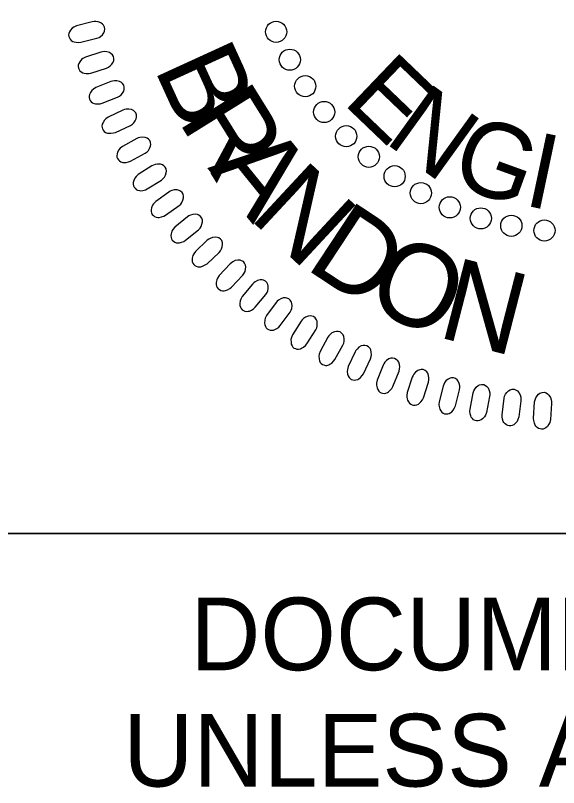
# Model space of a CAD drawing. Extents: x 505602 to 507548, y 483109 to 484209.
# Drawn here: x 507076.9 to 507118, y 484026.9 to 484085.4 of the extents above; entities that cross this region are included whole.
import ezdxf

# ---------------------------------------------------------------- set-up
doc = ezdxf.new("R2010")
doc.units = 0
for name, color, linetype in [('Sheet PE Seal Cell', 7, 'Continuous'), ('Sheet Profile CELL', 7, 'Continuous'), ('Sheet Sticker Exception Certification CELL', 7, 'Continuous')]:
    doc.layers.add(name, color=color, linetype=linetype)

msp = doc.modelspace()

# ---------------------------------------------------------------- linework, layer by layer
at = {"layer": 'Sheet PE Seal Cell'}
for points in [[(507082.689, 484084.884), (507081.501, 484084.579), (507081.298, 484084.488), (507081.175, 484084.403), (507081.039, 484084.252), (507080.957, 484084.131), (507080.907, 484084.002), (507080.895, 484083.891), (507080.903, 484083.777), (507080.95, 484083.674), (507081.009, 484083.566), (507081.093, 484083.479), (507081.216, 484083.403), (507081.308, 484083.364), (507081.469, 484083.336), (507081.658, 484083.323), (507081.818, 484083.341), (507083.037, 484083.645), (507083.196, 484083.709), (507083.32, 484083.788), (507083.452, 484083.914), (507083.56, 484084.057), (507083.613, 484084.171), (507083.632, 484084.339), (507083.614, 484084.488), (507083.538, 484084.623), (507083.464, 484084.712), (507083.336, 484084.811), (507083.142, 484084.884), (507082.951, 484084.905), (507082.818, 484084.901)], [(507083.343, 484082.6), (507082.176, 484082.221), (507081.979, 484082.118), (507081.862, 484082.026), (507081.735, 484081.866), (507081.661, 484081.739), (507081.62, 484081.608), (507081.615, 484081.497), (507081.63, 484081.384), (507081.684, 484081.284), (507081.749, 484081.179), (507081.838, 484081.098), (507081.966, 484081.03), (507082.059, 484080.997), (507082.223, 484080.979), (507082.412, 484080.978), (507082.571, 484081.005), (507083.768, 484081.386), (507083.922, 484081.46), (507084.042, 484081.546), (507084.165, 484081.68), (507084.263, 484081.83), (507084.31, 484081.947), (507084.318, 484082.115), (507084.291, 484082.263), (507084.207, 484082.393), (507084.127, 484082.477), (507083.993, 484082.567), (507083.795, 484082.629), (507083.603, 484082.637), (507083.471, 484082.625)], [(507084.102, 484080.363), (507082.961, 484079.912), (507082.77, 484079.796), (507082.659, 484079.696), (507082.543, 484079.529), (507082.477, 484079.398), (507082.444, 484079.265), (507082.446, 484079.153), (507082.468, 484079.041), (507082.528, 484078.945), (507082.6, 484078.844), (507082.693, 484078.769), (507082.825, 484078.709), (507082.921, 484078.682), (507083.086, 484078.675), (507083.274, 484078.685), (507083.431, 484078.723), (507084.602, 484079.178), (507084.752, 484079.261), (507084.865, 484079.355), (507084.98, 484079.496), (507085.069, 484079.652), (507085.108, 484079.772), (507085.105, 484079.94), (507085.069, 484080.087), (507084.977, 484080.21), (507084.892, 484080.29), (507084.753, 484080.371), (507084.551, 484080.419), (507084.359, 484080.416), (507084.228, 484080.396)], [(507085.001, 484078.203), (507083.891, 484077.681), (507083.709, 484077.554), (507083.604, 484077.447), (507083.499, 484077.273), (507083.441, 484077.139), (507083.416, 484077.003), (507083.425, 484076.892), (507083.454, 484076.782), (507083.52, 484076.689), (507083.598, 484076.594), (507083.697, 484076.524), (507083.832, 484076.472), (507083.929, 484076.452), (507084.093, 484076.455), (507084.281, 484076.477), (507084.435, 484076.524), (507085.576, 484077.052), (507085.719, 484077.145), (507085.827, 484077.245), (507085.932, 484077.393), (507086.012, 484077.554), (507086.043, 484077.677), (507086.03, 484077.844), (507085.984, 484077.988), (507085.884, 484078.106), (507085.794, 484078.18), (507085.651, 484078.253), (507085.446, 484078.288), (507085.255, 484078.273), (507085.125, 484078.245)], [(507086.049, 484076.054), (507084.973, 484075.464), (507084.799, 484075.326), (507084.702, 484075.212), (507084.607, 484075.033), (507084.558, 484074.894), (507084.542, 484074.758), (507084.557, 484074.647), (507084.594, 484074.539), (507084.666, 484074.451), (507084.75, 484074.36), (507084.852, 484074.297), (507084.99, 484074.254), (507085.089, 484074.239), (507085.252, 484074.253), (507085.438, 484074.287), (507085.589, 484074.343), (507086.694, 484074.942), (507086.832, 484075.044), (507086.932, 484075.15), (507087.029, 484075.305), (507087.097, 484075.471), (507087.121, 484075.595), (507087.097, 484075.761), (507087.043, 484075.902), (507086.936, 484076.013), (507086.842, 484076.081), (507086.693, 484076.145), (507086.487, 484076.167), (507086.297, 484076.14), (507086.169, 484076.104)], [(507087.205, 484073.98), (507086.169, 484073.322), (507086.003, 484073.174), (507085.914, 484073.055), (507085.83, 484072.869), (507085.79, 484072.729), (507085.783, 484072.591), (507085.805, 484072.481), (507085.848, 484072.376), (507085.926, 484072.292), (507086.015, 484072.207), (507086.121, 484072.151), (507086.261, 484072.116), (507086.36, 484072.108), (507086.523, 484072.131), (507086.707, 484072.177), (507086.853, 484072.243), (507087.919, 484072.91), (507088.05, 484073.019), (507088.144, 484073.133), (507088.23, 484073.294), (507088.288, 484073.463), (507088.304, 484073.588), (507088.27, 484073.753), (507088.207, 484073.89), (507088.093, 484073.994), (507087.995, 484074.056), (507087.842, 484074.11), (507087.635, 484074.12), (507087.447, 484074.081), (507087.322, 484074.036)], [(507088.482, 484072.005), (507087.488, 484071.284), (507087.333, 484071.125), (507087.25, 484071.001), (507087.179, 484070.81), (507087.148, 484070.667), (507087.149, 484070.529), (507087.178, 484070.422), (507087.228, 484070.318), (507087.31, 484070.24), (507087.405, 484070.161), (507087.515, 484070.111), (507087.657, 484070.085), (507087.756, 484070.084), (507087.917, 484070.117), (507088.097, 484070.174), (507088.24, 484070.249), (507089.261, 484070.982), (507089.385, 484071.1), (507089.471, 484071.218), (507089.548, 484071.384), (507089.595, 484071.557), (507089.603, 484071.683), (507089.559, 484071.845), (507089.487, 484071.978), (507089.367, 484072.075), (507089.265, 484072.13), (507089.11, 484072.175), (507088.903, 484072.172), (507088.717, 484072.121), (507088.595, 484072.069)], [(507089.885, 484070.123), (507088.939, 484069.342), (507088.794, 484069.173), (507088.72, 484069.044), (507088.661, 484068.85), (507088.638, 484068.705), (507088.648, 484068.568), (507088.684, 484068.462), (507088.74, 484068.362), (507088.827, 484068.289), (507088.926, 484068.216), (507089.039, 484068.173), (507089.182, 484068.156), (507089.282, 484068.161), (507089.44, 484068.204), (507089.616, 484068.273), (507089.754, 484068.356), (507090.727, 484069.152), (507090.844, 484069.277), (507090.922, 484069.401), (507090.988, 484069.571), (507091.025, 484069.747), (507091.024, 484069.872), (507090.97, 484070.032), (507090.89, 484070.16), (507090.764, 484070.249), (507090.659, 484070.298), (507090.501, 484070.333), (507090.295, 484070.317), (507090.113, 484070.254), (507089.994, 484070.195)], [(507091.395, 484068.353), (507090.5, 484067.513), (507090.366, 484067.337), (507090.3, 484067.203), (507090.253, 484067.005), (507090.24, 484066.859), (507090.258, 484066.722), (507090.301, 484066.618), (507090.363, 484066.523), (507090.454, 484066.455), (507090.558, 484066.388), (507090.673, 484066.353), (507090.818, 484066.345), (507090.916, 484066.356), (507091.072, 484066.409), (507091.244, 484066.489), (507091.375, 484066.581), (507092.296, 484067.436), (507092.405, 484067.568), (507092.476, 484067.697), (507092.531, 484067.871), (507092.556, 484068.048), (507092.548, 484068.173), (507092.484, 484068.33), (507092.396, 484068.452), (507092.265, 484068.534), (507092.157, 484068.576), (507091.997, 484068.6), (507091.792, 484068.571), (507091.614, 484068.497), (507091.5, 484068.43)], [(507093.131, 484066.575), (507092.29, 484065.681), (507092.167, 484065.495), (507092.11, 484065.358), (507092.075, 484065.157), (507092.071, 484065.01), (507092.098, 484064.876), (507092.147, 484064.776), (507092.215, 484064.684), (507092.31, 484064.622), (507092.419, 484064.562), (507092.535, 484064.533), (507092.68, 484064.535), (507092.778, 484064.552), (507092.93, 484064.614), (507093.096, 484064.705), (507093.222, 484064.805), (507094.088, 484065.716), (507094.187, 484065.855), (507094.25, 484065.988), (507094.294, 484066.165), (507094.308, 484066.343), (507094.292, 484066.468), (507094.219, 484066.619), (507094.123, 484066.737), (507093.987, 484066.81), (507093.876, 484066.845), (507093.716, 484066.86), (507093.513, 484066.817), (507093.34, 484066.733), (507093.23, 484066.659)], [(507094.821, 484065.045), (507094.038, 484064.099), (507093.927, 484063.906), (507093.878, 484063.766), (507093.856, 484063.564), (507093.862, 484063.417), (507093.897, 484063.284), (507093.952, 484063.186), (507094.026, 484063.099), (507094.124, 484063.044), (507094.236, 484062.991), (507094.354, 484062.97), (507094.499, 484062.98), (507094.596, 484063.003), (507094.743, 484063.075), (507094.903, 484063.175), (507095.023, 484063.284), (507095.83, 484064.248), (507095.921, 484064.392), (507095.974, 484064.529), (507096.008, 484064.709), (507096.011, 484064.887), (507095.986, 484065.012), (507095.903, 484065.157), (507095.801, 484065.268), (507095.661, 484065.332), (507095.547, 484065.361), (507095.386, 484065.365), (507095.187, 484065.311), (507095.019, 484065.215), (507094.914, 484065.135)], [(507096.601, 484063.644), (507095.88, 484062.651), (507095.781, 484062.452), (507095.741, 484062.308), (507095.732, 484062.105), (507095.747, 484061.959), (507095.79, 484061.829), (507095.851, 484061.735), (507095.93, 484061.653), (507096.033, 484061.603), (507096.148, 484061.557), (507096.267, 484061.544), (507096.41, 484061.563), (507096.506, 484061.592), (507096.648, 484061.674), (507096.802, 484061.784), (507096.914, 484061.9), (507097.659, 484062.912), (507097.74, 484063.062), (507097.786, 484063.202), (507097.808, 484063.383), (507097.8, 484063.562), (507097.767, 484063.683), (507097.676, 484063.825), (507097.566, 484063.929), (507097.422, 484063.984), (507097.308, 484064.005), (507097.147, 484064), (507096.95, 484063.932), (507096.79, 484063.827), (507096.69, 484063.739)], [(507098.503, 484062.231), (507097.846, 484061.195), (507097.759, 484060.99), (507097.728, 484060.844), (507097.732, 484060.64), (507097.756, 484060.496), (507097.808, 484060.369), (507097.874, 484060.278), (507097.959, 484060.202), (507098.063, 484060.159), (507098.181, 484060.119), (507098.301, 484060.114), (507098.443, 484060.142), (507098.536, 484060.178), (507098.673, 484060.267), (507098.82, 484060.387), (507098.924, 484060.51), (507099.604, 484061.567), (507099.676, 484061.722), (507099.713, 484061.864), (507099.723, 484062.046), (507099.703, 484062.224), (507099.663, 484062.344), (507099.564, 484062.479), (507099.448, 484062.575), (507099.3, 484062.622), (507099.185, 484062.636), (507099.025, 484062.62), (507098.833, 484062.541), (507098.679, 484062.425), (507098.585, 484062.332)], [(507100.521, 484061.015), (507099.93, 484059.941), (507099.857, 484059.73), (507099.835, 484059.583), (507099.852, 484059.38), (507099.884, 484059.237), (507099.944, 484059.113), (507100.016, 484059.028), (507100.105, 484058.956), (507100.212, 484058.92), (507100.332, 484058.888), (507100.452, 484058.89), (507100.592, 484058.927), (507100.683, 484058.968), (507100.814, 484059.067), (507100.953, 484059.195), (507101.05, 484059.324), (507101.662, 484060.422), (507101.723, 484060.581), (507101.751, 484060.725), (507101.75, 484060.908), (507101.72, 484061.084), (507101.673, 484061.201), (507101.564, 484061.329), (507101.442, 484061.419), (507101.292, 484061.456), (507101.176, 484061.463), (507101.017, 484061.437), (507100.831, 484061.345), (507100.685, 484061.221), (507100.596, 484061.122)], [(507102.58, 484059.909), (507102.058, 484058.799), (507101.998, 484058.585), (507101.986, 484058.436), (507102.015, 484058.234), (507102.056, 484058.094), (507102.124, 484057.974), (507102.201, 484057.894), (507102.295, 484057.828), (507102.404, 484057.798), (507102.525, 484057.774), (507102.645, 484057.784), (507102.783, 484057.83), (507102.871, 484057.876), (507102.995, 484057.983), (507103.126, 484058.119), (507103.215, 484058.254), (507103.757, 484059.388), (507103.808, 484059.551), (507103.827, 484059.696), (507103.814, 484059.879), (507103.773, 484060.053), (507103.718, 484060.167), (507103.602, 484060.288), (507103.474, 484060.37), (507103.323, 484060.397), (507103.206, 484060.396), (507103.049, 484060.361), (507102.869, 484060.258), (507102.732, 484060.124), (507102.65, 484060.02)], [(507104.708, 484058.901), (507104.256, 484057.76), (507104.21, 484057.542), (507104.207, 484057.393), (507104.249, 484057.194), (507104.298, 484057.056), (507104.374, 484056.941), (507104.456, 484056.865), (507104.553, 484056.805), (507104.664, 484056.783), (507104.787, 484056.767), (507104.906, 484056.783), (507105.04, 484056.838), (507105.125, 484056.89), (507105.243, 484057.004), (507105.364, 484057.149), (507105.444, 484057.289), (507105.914, 484058.455), (507105.956, 484058.62), (507105.965, 484058.766), (507105.941, 484058.948), (507105.888, 484059.119), (507105.827, 484059.229), (507105.703, 484059.343), (507105.571, 484059.416), (507105.418, 484059.434), (507105.302, 484059.426), (507105.147, 484059.381), (507104.974, 484059.267), (507104.845, 484059.124), (507104.77, 484059.015)], [(507106.917, 484057.999), (507106.537, 484056.832), (507106.505, 484056.611), (507106.511, 484056.463), (507106.565, 484056.266), (507106.624, 484056.132), (507106.706, 484056.022), (507106.793, 484055.952), (507106.894, 484055.898), (507107.006, 484055.882), (507107.13, 484055.874), (507107.247, 484055.898), (507107.378, 484055.961), (507107.459, 484056.018), (507107.57, 484056.14), (507107.682, 484056.292), (507107.753, 484056.436), (507108.149, 484057.629), (507108.18, 484057.798), (507108.18, 484057.944), (507108.144, 484058.123), (507108.081, 484058.291), (507108.013, 484058.397), (507107.882, 484058.502), (507107.746, 484058.568), (507107.592, 484058.576), (507107.477, 484058.56), (507107.325, 484058.505), (507107.159, 484058.381), (507107.039, 484058.231), (507106.971, 484058.117)], [(507109.25, 484057.325), (507108.944, 484056.137), (507108.926, 484055.916), (507108.941, 484055.767), (507109.008, 484055.575), (507109.074, 484055.445), (507109.164, 484055.34), (507109.255, 484055.275), (507109.358, 484055.228), (507109.472, 484055.22), (507109.595, 484055.219), (507109.711, 484055.25), (507109.837, 484055.321), (507109.915, 484055.382), (507110.018, 484055.511), (507110.12, 484055.67), (507110.182, 484055.819), (507110.502, 484057.034), (507110.522, 484057.204), (507110.513, 484057.351), (507110.466, 484057.527), (507110.393, 484057.69), (507110.318, 484057.792), (507110.181, 484057.889), (507110.042, 484057.945), (507109.886, 484057.944), (507109.773, 484057.922), (507109.625, 484057.857), (507109.467, 484057.722), (507109.357, 484057.565), (507109.296, 484057.447)], [(507112.772, 484056.538), (507112.541, 484055.333), (507112.463, 484055.124), (507112.386, 484054.997), (507112.244, 484054.851), (507112.128, 484054.762), (507112.003, 484054.705), (507111.892, 484054.685), (507111.778, 484054.687), (507111.673, 484054.727), (507111.56, 484054.779), (507111.469, 484054.857), (507111.385, 484054.975), (507111.341, 484055.065), (507111.303, 484055.224), (507111.278, 484055.412), (507111.286, 484055.573), (507111.514, 484056.808), (507111.568, 484056.971), (507111.639, 484057.099), (507111.757, 484057.239), (507111.893, 484057.355), (507112.003, 484057.416), (507112.168, 484057.445), (507112.32, 484057.436), (507112.458, 484057.369), (507112.552, 484057.3), (507112.658, 484057.179), (507112.743, 484056.99), (507112.776, 484056.801), (507112.781, 484056.668)], [(507115.138, 484056.212), (507114.983, 484054.995), (507114.919, 484054.782), (507114.849, 484054.649), (507114.717, 484054.495), (507114.607, 484054.399), (507114.485, 484054.333), (507114.377, 484054.307), (507114.263, 484054.302), (507114.155, 484054.336), (507114.039, 484054.38), (507113.943, 484054.452), (507113.852, 484054.565), (507113.802, 484054.652), (507113.754, 484054.809), (507113.718, 484054.994), (507113.715, 484055.155), (507113.866, 484056.402), (507113.909, 484056.568), (507113.972, 484056.701), (507114.08, 484056.848), (507114.209, 484056.973), (507114.316, 484057.039), (507114.479, 484057.079), (507114.63, 484057.08), (507114.773, 484057.021), (507114.871, 484056.959), (507114.985, 484056.844), (507115.081, 484056.661), (507115.126, 484056.474), (507115.139, 484056.342)], [(507117.455, 484056.014), (507117.377, 484054.79), (507117.326, 484054.574), (507117.265, 484054.437), (507117.143, 484054.275), (507117.039, 484054.171), (507116.922, 484054.099), (507116.815, 484054.066), (507116.701, 484054.053), (507116.591, 484054.081), (507116.474, 484054.117), (507116.373, 484054.183), (507116.275, 484054.29), (507116.22, 484054.373), (507116.162, 484054.527), (507116.114, 484054.71), (507116.102, 484054.871), (507116.173, 484056.125), (507116.207, 484056.293), (507116.261, 484056.429), (507116.36, 484056.583), (507116.48, 484056.716), (507116.583, 484056.789), (507116.743, 484056.838), (507116.894, 484056.849), (507117.041, 484056.799), (507117.141, 484056.743), (507117.262, 484056.636), (507117.37, 484056.459), (507117.427, 484056.275), (507117.448, 484056.145)]]:
    msp.add_lwpolyline(points, close=True, dxfattribs=at)
for centre in [(507096.606, 484084.132), (507097.641, 484082.02), (507098.81, 484080.016), (507100.242, 484078.063), (507101.914, 484076.23), (507103.625, 484074.676), (507105.576, 484073.202), (507107.566, 484071.926), (507109.755, 484070.85), (507112.104, 484070.013), (507114.413, 484069.454), (507116.921, 484069.095)]:
    msp.add_circle(centre, 0.801, dxfattribs=at)
at = {"layer": 'Sheet Profile CELL'}
msp.add_lwpolyline([(507069.03, 484158.662), (507169.08, 484158.662), (507169.08, 484046.162), (507069.03, 484046.162)], close=True, dxfattribs=at)
at = {"layer": 'Sheet Sticker Exception Certification CELL'}
msp.add_line((507069.03, 484046.162), (507269.067, 484046.162), dxfattribs=at)
msp.add_line((507069.03, 484046.162), (507269.067, 484046.162), dxfattribs=at)

# ---------------------------------------------------------------- texts
at = {"layer": 'Sheet PE Seal Cell'}
for s, height, rotation, p in [('B', 6.236, 294.5897, (507087.323, 484081.403)), ('E', 5.669, 316.26559, (507101.563, 484078.782)), ('R', 6.236, 301.86473, (507089.134, 484077.446)), ('N', 5.669, 324.20538, (507104.698, 484075.826)), ('G', 5.669, 340.08498, (507109.592, 484072.728)), ('I', 5.669, 348.02477, (507115.221, 484071.038)), ('A', 6.236, 308.98157, (507091.377, 484073.828)), ('N', 6.236, 317.09274, (507094.456, 484070.08)), ('D', 6.236, 326.58243, (507098.686, 484066.299)), ('O', 6.236, 335.45066, (507103.152, 484063.441)), ('N', 6.236, 345.5505, (507108.704, 484061.069))]:
    msp.add_text(s, height=height, rotation=rotation, dxfattribs=at).set_placement(p)
at = {"layer": 'Sheet Sticker Exception Certification CELL'}
for s, p in [('DOCUMENT NOT CONSIDERED FINAL', (507090.101, 484035.816)), ('DOCUMENT NOT CONSIDERED FINAL', (507090.101, 484035.816)), ('UNLESS ALL SIGNATURES COMPLETED', (507085.03, 484027.016)), ('UNLESS ALL SIGNATURES COMPLETED', (507085.03, 484027.016))]:
    msp.add_text(s, height=5.5, dxfattribs=at).set_placement(p)

doc.saveas('drawing.dxf')
